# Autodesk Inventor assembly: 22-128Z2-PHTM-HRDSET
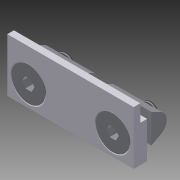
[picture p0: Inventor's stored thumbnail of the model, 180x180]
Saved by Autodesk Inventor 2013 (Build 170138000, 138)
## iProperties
Created: 2004-11
Part Number: 22-128Z2-PHTM-HRDSET
Document SubType Name: Assembly
Designer: Autodesk, Inc.
Manufacturer: Standard
Standards Organization: Custom
Mass: 58.1749 g
Surface Area: 79.3691 cm^2
Volume: 11.8884 cm^3
Density: 4.89343 g/cm^3
CAGE: 1LJX3
Dept. ID: Product Design
Description #2: ---
Finish #1: ---
Finish #2: ---
Material ID: ---
Project Number: ---
Author: Autodesk, Inc.
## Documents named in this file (6)
- Z:\_DATEN\Test Station\Components\22-128Z2 Hardware Set.iam
- Z:\_DATEN\Test Station\Components\22-128Z2.ipt
- Z:\_DATEN\Test Station\Components\24-218-8.ipt
- Z:\_DATEN\Test Station\Components\20-058.ipt
- C:\Users\kelleyb.ADS\Desktop\Samples MIGRATED 2009 224 RTM_1\Standard Parts\Test Station Content\Fastners\2X-YYY-ZZ IPS Screws.ipt
- C:\Users\kelleyb.ADS\Desktop\Samples MIGRATED 2009 224 RTM_1\Standard Parts\Test Station Content\Fastners\20-XXX TSlot Nuts.ipt
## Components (5 placed, 3 different names)
1. 22-128Z2:1 — Insert:1, Mate:2, Angle:1, Insert:2, Angle:2
2. 24-218-8:1 — Insert:1, Mate:1
3. 20-058:1 — Mate:1, Mate:2, Angle:1, Flush:1
4. 24-218-8:3 — Insert:2, Mate:3
5. 20-058:2 — Mate:3, Flush:1, Angle:2
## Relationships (8: Mate 3, Insert 2, Angle 2, Flush 1)
- Insert:1: 22-128Z2:1 ↔ 24-218-8:1
- Mate:1: 24-218-8:1 ↔ 20-058:1
- Mate:2: 22-128Z2:1 ↔ 20-058:1
- Angle:1: 22-128Z2:1 ↔ 20-058:1
- Insert:2: 22-128Z2:1 ↔ 24-218-8:3
- Mate:3: 24-218-8:3 ↔ 20-058:2
- Flush:1: 20-058:1 ↔ 20-058:2
- Angle:2: 22-128Z2:1 ↔ 20-058:2
